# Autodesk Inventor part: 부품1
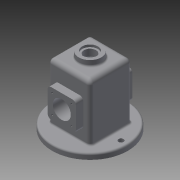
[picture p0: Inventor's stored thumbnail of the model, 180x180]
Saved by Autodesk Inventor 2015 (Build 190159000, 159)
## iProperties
Created: 2021-08
Part Number: 부품1
Material: 일반
Document SubType Name: Modeling
Designer: 104658
Density: 1 g/cm^3
Appearance: 기본값
Author: 104658
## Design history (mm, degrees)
sketch "스케치1"
  geometry: C1 r 67 at (0, 0); 1 further point
  constraints: 1 centre point, 1 coincident
  dimensions: "d0" = 134 diameter of C1
extrude "돌출1" new body sketch "스케치1" distance "d1" = 10; taper "d2" = 0 deg
sketch "스케치3"
  geometry: L1 (-37, -37)-(37, -37); L2 (37, -37)-(37, 37); L3 (37, 37)-(-37, 37); L4 (-37, 37)-(-37, -37); L5 (-37, -37)-(37, 37); L6 (37, -37)-(-37, 37); C1 r 67 at (0, 0) reference
  constraints: 12 end point, 2 midpoint, 2 parallel, 1 horizontal, 1 perpendicular
  dimensions: "d3" = 74 distance of L2.end L3.end; "d4" = 74 distance of L1.end L2.end
extrude "돌출2" join sketch "스케치3" distance "d5" = 100; taper "d6" = 0 deg
sketch "스케치6"
  geometry: 1 further point
sketch "스케치7"
  geometry: L1 (32, -32)-(-32, -32); L2 (-32, -32)-(-32, 32); L3 (-32, 32)-(32, 32); L4 (32, 32)-(32, -32); L5 (32, -32)-(-32, 32); L6 (-32, -32)-(32, 32); C1 r 67 at (0, 0) reference
  constraints: 12 end point, 2 midpoint, 2 parallel, 1 horizontal, 1 perpendicular
  dimensions: "d15" = 64 distance of L2.end L3.end; "d16" = 64 distance of L1.end L2.end
extrude "돌출5" cut sketch "스케치7" distance "d17" = 105; taper "d18" = 0 deg
sketch "스케치9"
  geometry: L1 (12, 70)-(62, 70); L2 (62, 70)-(62, 20); L3 (62, 20)-(12, 20); L4 (12, 20)-(12, 70); L5 (12, 70)-(62, 20); L6 (62, 70)-(12, 20); L7 (-30, -10)-(104, -10) reference; 4 further points
  constraints: 12 end point, 4 midpoint, 2 parallel, 1 horizontal, 1 perpendicular, 1 vertical alignment
  dimensions: "d24" = 55 distance from line of point (37, 45) L7; "d25" = 50 distance of L1.end L2.end; "d26" = 50 distance between parallel lines of L4 L2
extrude "돌출7" join sketch "스케치9" distance "d27" = 13; taper "d28" = 0 deg
sketch "스케치10"
  geometry: L1 (0, 0)-(64, 0) reference; L2 (0, 0)-(0, -105) reference; L3 (0, -105)-(64, -105) reference; L4 (64, 0)-(64, -105) reference; 1 further point
sketch "스케치11"
  geometry: L1 (0, 0)-(64, 0) reference; C1 r 25 at (32, -55); 2 further points
  constraints: 1 centre point, 1 midpoint, 1 vertical alignment
  dimensions: "d29" = 55 distance from line of C1.centre L1; "d30" = 50 diameter of C1
extrude "돌출8" join sketch "스케치11" distance "d31" = 7; taper "d32" = 0 deg
sketch "스케치12"
  geometry: L1 (-25, 30)-(-25, 80) reference; L2 (32, 0)-(-32, 0) reference; L3 (32, 0)-(32, 105) reference; L4 (32, 105)-(-32, 105) reference; L5 (-32, 0)-(-32, 105) reference; L6 (-32, 80)-(-25, 80) reference; L7 (-32, 30)-(-25, 30) reference; L8 (-50, 80)-(-50, 30) reference; L9 (-37, 80)-(-50, 80) reference; L10 (-50, 55)-(-25, 55); L11 (-32, 30)-(-25, 32.548); L12 (-25, 30)-(-32, 30); L13 (-32, 0)-(-32, 105) reference; L14 (-25, 32.548)-(-25, 30); 1 further point
  constraints: 8 end point, 2 midpoint, 1 collinear, 1 perpendicular, 1 point on line
  dimensions: "d33" = 110 deg angle of L11 L5
revolve "회전1" sketch "스케치12" stored, may be unused: angle "d34" = 90 deg
fillet "모깎기1" dims "d35" = 3
sketch "스케치13"
  geometry: L1 (-30, -10)-(104, -10) reference; 3 further points
  constraints: 1 midpoint, 1 vertical alignment
  dimensions: "d36" = 55 distance from line of point (37, 45) L1
hole "구멍1" sketch "스케치13" at (37, 45) diameter "d37" = 32; stored, may be unused: countersink angle "d41" = 90 deg, drill point angle "d43" = 118 deg; dims "d38" = 6, "d39" = 4, "d40" = 2, "d42" = 8
fillet "모깎기2" dims "d44" = 6
fillet "모깎기3" dims "d45" = 6
fillet "모깎기4" dims "d46" = 6
fillet "모깎기5" dims "d47" = 8
sketch "스케치14"
  geometry: 1 further point
hole "구멍2" sketch "스케치14" at (-55, 0) diameter "d49" = 9; stored, may be unused: countersink angle "d53" = 90 deg, drill point angle "d55" = 118 deg; dims "d50" = 6, "d51" = 4, "d52" = 2, "d54" = 8
sketch "스케치15"
  geometry: C1 r 16 at (37, 45) reference; 2 further points
  dimensions: "d56" = 17 horizontal distance of point (54, 62) C1.centre; "d57" = 17 horizontal distance of point (54, 62) C1.centre
hole "구멍3" sketch "스케치15" at (54, 62) diameter "d58" = 3.242; stored, may be unused: countersink angle "d62" = 90 deg, drill point angle "d64" = 118 deg; dims "d59" = 8, "d60" = 4, "d61" = 2, "d63" = 10
sketch "스케치18"
  geometry: L1 (19.488, -110)-(42.512, -110) reference; 2 further points
  constraints: 1 other
  dimensions: "d74" = 28 distance from line of point (31.154, -82) L1
feature "엠보싱1" sketch "스케치18" dims "d15" = 64, "d16" = 64, "d75" = 0.5, "d76" = 0
sketch "스케치20"
  geometry: C1 r 20 at (0, 0); 1 further point
  constraints: 1 centre point, 1 coincident
  dimensions: "d77" = 40 diameter of C1
extrude "돌출10" join sketch "스케치20" distance "d78" = 10; taper "d79" = 0 deg
sketch "스케치21"
  geometry: C1 r 20 at (0, 0) reference; 1 further point
  constraints: 1 coincident
hole "구멍4" sketch "스케치21" at (0, 0) diameter "d80" = 21; stored, may be unused: countersink angle "d84" = 90 deg, drill point angle "d86" = 118 deg; dims "d81" = 21, "d82" = 28, "d83" = 4, "d85" = 24.8
fillet "모깎기7" dims "d87" = 3
fillet "모깎기8" dims "d88" = 3
sketch "스케치22"
  geometry: 1 further point
sketch "스케치23"
  geometry: 1 further point
sketch "스케치24"
  geometry: C1 r 16 at (0, 0) reference; 2 further points
  constraints: 1 coincident
hole "구멍5" sketch "스케치24" at (0, 0) diameter "d89" = 32; stored, may be unused: countersink angle "d93" = 90 deg, drill point angle "d95" = 118 deg; dims "d90" = 21, "d91" = 28, "d92" = 4, "d94" = 24.8
node "솔리드1"
mirror "대칭1"
mirror "대칭2"
pattern_circular "원형 패턴1" dims angle "d66" = 360 deg
mirror "대칭3"
mirror "대칭4"
mirror "대칭5"
node "투영된 루프3"
